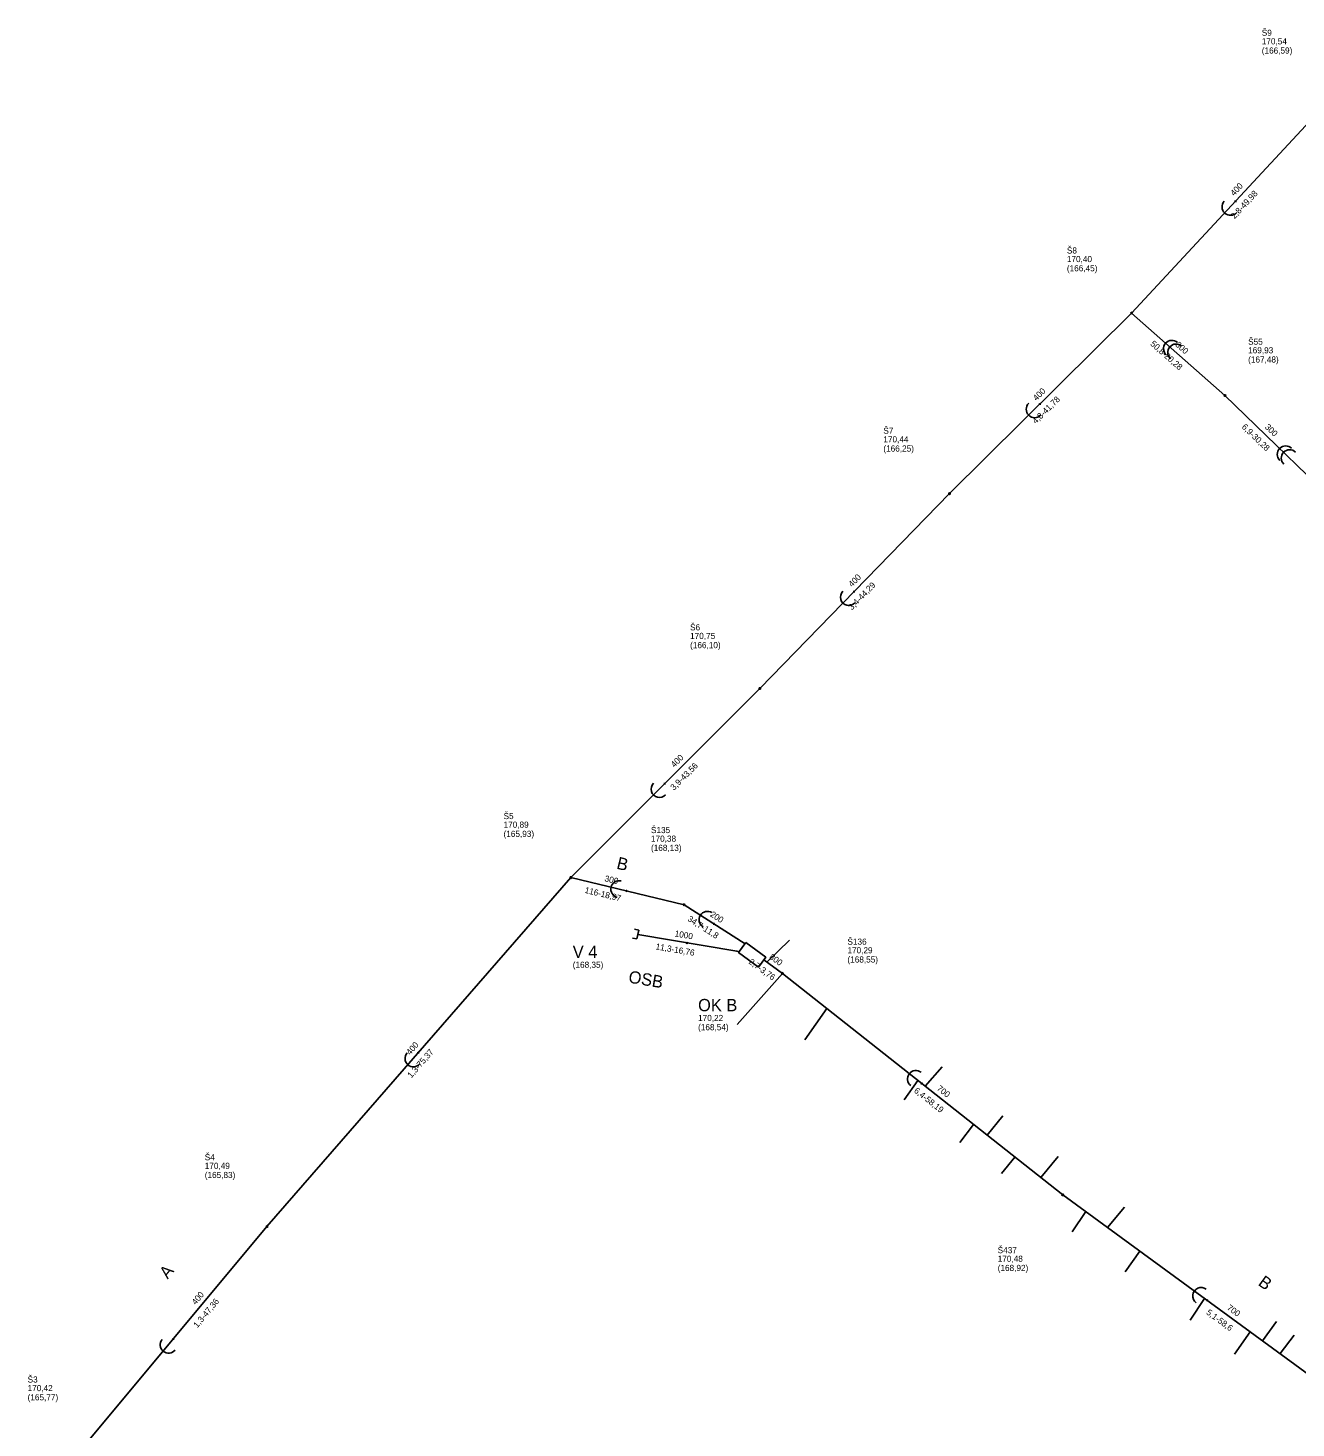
# Model space of a CAD drawing. Extents: x -548529 to -543591, y -1201432 to -1192608.
# Drawn here: x -547521.7 to -547315.1, y -1195273.8 to -1195045.7 of the extents above; entities that cross this region are included whole.
import ezdxf

# ---------------------------------------------------------------- set-up
doc = ezdxf.new("R2010")
doc.units = 0
for name, color, linetype in [('C3D_Bod-Značky', 7, 'Continuous'), ('C3D_Koridor', 7, 'Continuous'), ('C3D_Křižovatka', 7, 'Continuous'), ('C3D_Netisknutelná', 7, 'Continuous'), ('C3D_Podsestava', 7, 'Continuous'), ('C3D_Povrch-Vrstevnice', 7, 'Continuous'), ('C3D_PP-Navrh', 7, 'Continuous'), ('C3D_PP-Popisek', 7, 'Continuous'), ('C3D_PP-zobrazeni v PR', 7, 'Continuous'), ('C3D_PR-Popisek', 7, 'Continuous'), ('C3D_SPR-Popisek', 7, 'Continuous'), ('C3D_Tlakove_potrubi_Popis', 7, 'Continuous'), ('C3D_ZPR-Formaty', 7, 'Continuous')]:
    doc.layers.add(name, color=color, linetype=linetype)

# ---------------------------------------------------------------- blocks, each defined once
blk = doc.blocks.new('100')
at = {"layer": 'Defpoints'}
blk.add_circle((0, 0), 0.127, dxfattribs=at)
blk = doc.blocks.new('96')
at = {"layer": 'Defpoints'}
for p, q in [((0, 0.72), (0, -0.72)), ((0, 0.72), (0.72, 0.72)), ((0.72, -0.72), (0, -0.72))]:
    blk.add_line(p, q, dxfattribs=at)
blk = doc.blocks.new('86')
at = {"layer": 'Defpoints'}
blk.add_lwpolyline([(0.08, 0.14), (0.19, 0), (0.08, -0.14)], dxfattribs=at)
blk.add_arc((1.37, 0), 1.37, 270, 90, dxfattribs=at)
blk = doc.blocks.new('92')
at = {"layer": 'Defpoints'}
for points in [[(-0.11, 0.138), (0, 0), (-0.11, -0.136)], [(0.039, 0.138), (0.149, 0), (0.039, -0.136)]]:
    blk.add_lwpolyline(points, dxfattribs=at)
blk = doc.blocks.new('88')
at = {"layer": 'Defpoints'}
for centre in [(0.47, 0), (1.37, 0)]:
    blk.add_arc(centre, 1.37, 270, 90, dxfattribs=at)
blk = doc.blocks.new('91')
at = {"layer": 'Defpoints'}
blk.add_lwpolyline([(0.08, 0.14), (0.19, 0), (0.08, -0.14)], dxfattribs=at)
blk.add_arc((1.37, 0), 1.37, 270, 90, dxfattribs=at)

msp = doc.modelspace()

# ---------------------------------------------------------------- linework, layer by layer
at = {"layer": 'C3D_Bod-Značky'}
for points in [[(-547307.83, -1195055.55), (-547341.85, -1195092.17)], [(-547341.85, -1195092.17), (-547371.53, -1195121.57)], [(-547371.53, -1195121.57), (-547402.42, -1195153.31)], [(-547402.42, -1195153.31), (-547433.22, -1195184.11)], [(-547433.22, -1195184.11), (-547482.72, -1195240.95)], [(-547414.77, -1195188.54), (-547433.22, -1195184.11)], [(-547404.818, -1195194.883), (-547414.77, -1195188.54)], [(-547398.75, -1195199.72), (-547401.794, -1195197.52)], [(-547353.081, -1195235.779), (-547398.75, -1195199.72)], [(-547305.756, -1195270.341), (-547353.081, -1195235.779)], [(-547482.72, -1195240.95), (-547513.05, -1195277.32)]]:
    msp.add_lwpolyline(points, dxfattribs=at)
at = {"layer": 'C3D_Koridor'}
for points in [[(-547401.294, -1195197.881), (-547397.59, -1195194.313)], [(-547398.75, -1195199.72), (-547406.135, -1195208.017)], [(-547391.527, -1195205.423), (-547395.095, -1195210.514)], [(-547375.481, -1195218.093), (-547372.703, -1195214.963)], [(-547376.659, -1195217.163), (-547378.891, -1195220.312)], [(-547365.405, -1195226.048), (-547362.828, -1195222.903)], [(-547367.589, -1195224.324), (-547369.848, -1195227.282)], [(-547360.868, -1195229.631), (-547363.038, -1195232.298)], [(-547356.669, -1195232.946), (-547353.81, -1195229.526)], [(-547349.322, -1195238.524), (-547351.561, -1195241.795)], [(-547345.796, -1195241.099), (-547342.999, -1195237.812)], [(-547340.535, -1195244.941), (-547342.883, -1195248.299)], [(-547329.967, -1195252.66), (-547332.296, -1195256.183)], [(-547322.52, -1195258.098), (-547325.085, -1195261.71)], [(-547320.532, -1195259.55), (-547318.242, -1195256.433)], [(-547317.654, -1195261.652), (-547315.353, -1195258.636)]]:
    msp.add_lwpolyline(points, dxfattribs=at)
at = {"layer": 'C3D_Podsestava'}
for points in [[(-547326.65, -1195105.6), (-547341.85, -1195092.17)], [(-547304.88, -1195126.65), (-547326.65, -1195105.6)]]:
    msp.add_lwpolyline(points, dxfattribs=at)
at = {"layer": 'C3D_Povrch-Vrstevnice'}
msp.add_lwpolyline([(-547405.779, -1195196.186), (-547406.175, -1195196.119), (-547422.3, -1195193.39)], dxfattribs=at)
at = {"layer": 'C3D_PP-Navrh'}
msp.add_lwpolyline([(-547404.691, -1195194.71), (-547401.472, -1195197.084), (-547402.659, -1195198.694), (-547405.878, -1195196.32), (-547404.691, -1195194.71)], dxfattribs=at)

# ---------------------------------------------------------------- block references
at = {"layer": 'C3D_PP-Navrh', "xscale": 1.008377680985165, "yscale": 1.0083776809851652, "rotation": 168.37362119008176}
msp.add_blockref('96', (-547422.3, -1195193.39), dxfattribs=at)
at = {"layer": 'C3D_PP-zobrazeni v PR'}
for p, xscale, yscale, rotation in [((-547341.85, -1195092.17), 1.00000001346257, 1.0000000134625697, -178.0000000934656), ((-547326.65, -1195105.6), 1.0000000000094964, 1.0000000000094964, 137.9999986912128), ((-547371.53, -1195121.57), 1.0000000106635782, 1.0000000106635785, -134.00000165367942), ((-547402.42, -1195153.31), 1.0000000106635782, 1.0000000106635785, -134.00000165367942), ((-547433.22, -1195184.11), 1.033506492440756, 1.033506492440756, -156.95871826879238), ((-547414.77, -1195188.54), 1.0225848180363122, 1.0225848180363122, 154.18102564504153), ((-547398.75, -1195199.72), 0.9999999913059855, 0.9999999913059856, 142.99999806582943), ((-547353.081, -1195235.779), 0.9999999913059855, 0.9999999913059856, 142.99999806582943), ((-547482.72, -1195240.95), 1.0000000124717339, 1.0000000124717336, 49.99999868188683)]:
    msp.add_blockref('100', p, dxfattribs=dict(at, xscale=xscale, yscale=yscale, rotation=rotation))
at = {"layer": 'C3D_SPR-Popisek'}
for name, p, xscale, yscale, rotation in [('86', (-547324.84, -1195073.86), 1.0000000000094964, 1.0000000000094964, -132.0000013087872), ('88', (-547334.25, -1195098.885), 1.0000000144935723, 1.0000000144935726, 139.00000089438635), ('86', (-547356.69, -1195106.87), 0.999999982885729, 0.9999999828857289, -135), ('88', (-547315.765, -1195116.125), 1.0000000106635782, 1.0000000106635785, 135.99999834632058), ('86', (-547386.975, -1195137.44), 1.0000000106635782, 1.0000000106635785, -134.00000165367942), ('86', (-547417.82, -1195168.71), 1.0000000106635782, 1.0000000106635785, -134.00000165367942), ('86', (-547423.995, -1195186.325), 1.0028916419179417, 1.0028916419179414, 166.30279126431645), ('86', (-547409.794, -1195191.712), 0.9999999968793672, 0.9999999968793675, 147.99999972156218), ('92', (-547414.237, -1195194.755), 1.008377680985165, 1.0083776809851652, 168.37362119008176), ('86', (-547457.97, -1195212.53), 1.0000000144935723, 1.0000000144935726, -130.99999910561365), ('91', (-547375.916, -1195217.75), 1.000000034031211, 1.0000000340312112, 141.99999959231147), ('91', (-547329.418, -1195253.06), 1.000000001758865, 1.000000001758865, 144.00000066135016), ('86', (-547497.885, -1195259.135), 1.000000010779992, 1.0000000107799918, -128.99999891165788)]:
    msp.add_blockref(name, p, dxfattribs=dict(at, xscale=xscale, yscale=yscale, rotation=rotation))

# ---------------------------------------------------------------- texts
at = {"layer": 'C3D_Křižovatka'}
for s, p in [('Š9', (-547320.65, -1195047.01)), ('Š8', (-547352.4, -1195082.47)), ('Š55', (-547322.87, -1195097.33)), ('Š7', (-547382.3, -1195111.83)), ('Š6', (-547413.79, -1195143.85)), ('Š5', (-547444.18, -1195174.59)), ('Š135', (-547420.16, -1195176.87)), ('Š136', (-547388.15, -1195195.05)), ('Š4', (-547492.86, -1195230.15)), ('Š437', (-547363.671, -1195245.289)), ('Š3', (-547521.72, -1195266.36))]:
    msp.add_text(s, height=1, dxfattribs=at).set_placement(p)
at = {"layer": 'C3D_Netisknutelná'}
for s, rotation, p in [('B', 346.5, (-547425.883, -1195182.645)), ('OSB', 350.39, (-547423.93, -1195201.202)), ('A', 50.17, (-547498.914, -1195249.591)), ('B', 323.86, (-547321.379, -1195250.388))]:
    msp.add_text(s, height=2, rotation=rotation, dxfattribs=at).set_placement(p)
at = {"layer": 'C3D_PP-Popisek'}
for s, height, p in [('V 4', 2, (-547432.91, -1195197.21)), ('(168,35)', 1, (-547432.91, -1195198.81)), ('OK B', 2, (-547412.486, -1195205.879)), ('(168,54)', 1, (-547412.486, -1195208.979)), ('170,22 ', 1, (-547412.486, -1195207.479))]:
    msp.add_text(s, height=height, dxfattribs=at).set_placement(p)
at = {"layer": 'C3D_PR-Popisek'}
for s, rotation, p in [('400', 47.11, (-547325.152, -1195073.164)), ('300', 318.54, (-547334.821, -1195097.452)), ('400', 44.73, (-547357.354, -1195106.54)), ('300', 315.96, (-547320.238, -1195110.823)), ('400', 45.78, (-547387.401, -1195136.871)), ('400', 45, (-547416.338, -1195166.245)), ('300', 346.5, (-547427.796, -1195184.688)), ('200', 327.49, (-547410.623, -1195190.354)), ('1000', 350.39, (-547416.361, -1195193.688)), ('800', 324.14, (-547400.986, -1195197.237)), ('400', 48.95, (-547459.394, -1195213.095)), ('700', 321.71, (-547373.678, -1195218.628)), ('400', 50.17, (-547494.33, -1195253.784)), ('700', 323.86, (-547326.423, -1195254.38))]:
    msp.add_text(s, height=1, rotation=rotation, dxfattribs=at).set_placement(p)
at = {"layer": 'C3D_Tlakove_potrubi_Popis'}
for s, p in [('170,54 ', (-547320.65, -1195048.41)), ('(166,59)', (-547320.65, -1195049.91)), ('(166,45)', (-547352.4, -1195085.37)), ('170,40 ', (-547352.4, -1195083.87)), ('169,93 ', (-547322.87, -1195098.73)), ('(167,48)', (-547322.87, -1195100.23)), ('170,44 ', (-547382.3, -1195113.23)), ('(166,25)', (-547382.3, -1195114.73)), ('(166,10)', (-547413.79, -1195146.75)), ('170,75 ', (-547413.79, -1195145.25)), ('170,89 ', (-547444.18, -1195175.99)), ('(165,93)', (-547444.18, -1195177.49)), ('170,38 ', (-547420.16, -1195178.27)), ('(168,13)', (-547420.16, -1195179.77)), ('170,29 ', (-547388.15, -1195196.45)), ('(168,55)', (-547388.15, -1195197.95)), ('170,49 ', (-547492.86, -1195231.55)), ('(165,83)', (-547492.86, -1195233.05)), ('170,48 ', (-547363.671, -1195246.689)), ('(168,92)', (-547363.671, -1195248.189)), ('170,42 ', (-547521.72, -1195267.76)), ('(165,77)', (-547521.72, -1195269.26))]:
    msp.add_text(s, height=1, dxfattribs=at).set_placement(p)
at = {"layer": 'C3D_ZPR-Formaty'}
for s, rotation, p in [('2,8-49,98', 47.11, (-547325.084, -1195076.915)), ('50,8-20,28', 318.54, (-547338.899, -1195097.306)), ('4,8-41,78', 44.73, (-547357.447, -1195110.295)), ('6,9-30,28', 315.96, (-547323.993, -1195110.812)), ('3,4-44,29', 45.78, (-547387.421, -1195140.622)), ('3,9-43,56', 45, (-547416.417, -1195169.984)), ('116-18,97', 346.5, (-547431.028, -1195186.589)), ('34,7-11,8', 327.49, (-547414.302, -1195191.093)), ('11,3-16,76', 350.39, (-547419.457, -1195195.798)), ('2,7-3,76', 324.14, (-547404.33, -1195198.034)), ('1,3-75,37', 48.95, (-547459.202, -1195216.84)), ('6,4-58,19', 321.71, (-547377.404, -1195218.993)), ('1,3-47,36', 50.17, (-547494.065, -1195257.524)), ('5,1-58,6', 323.86, (-547329.786, -1195255.144))]:
    msp.add_text(s, height=1, rotation=rotation, dxfattribs=at).set_placement(p)

doc.saveas('drawing.dxf')
